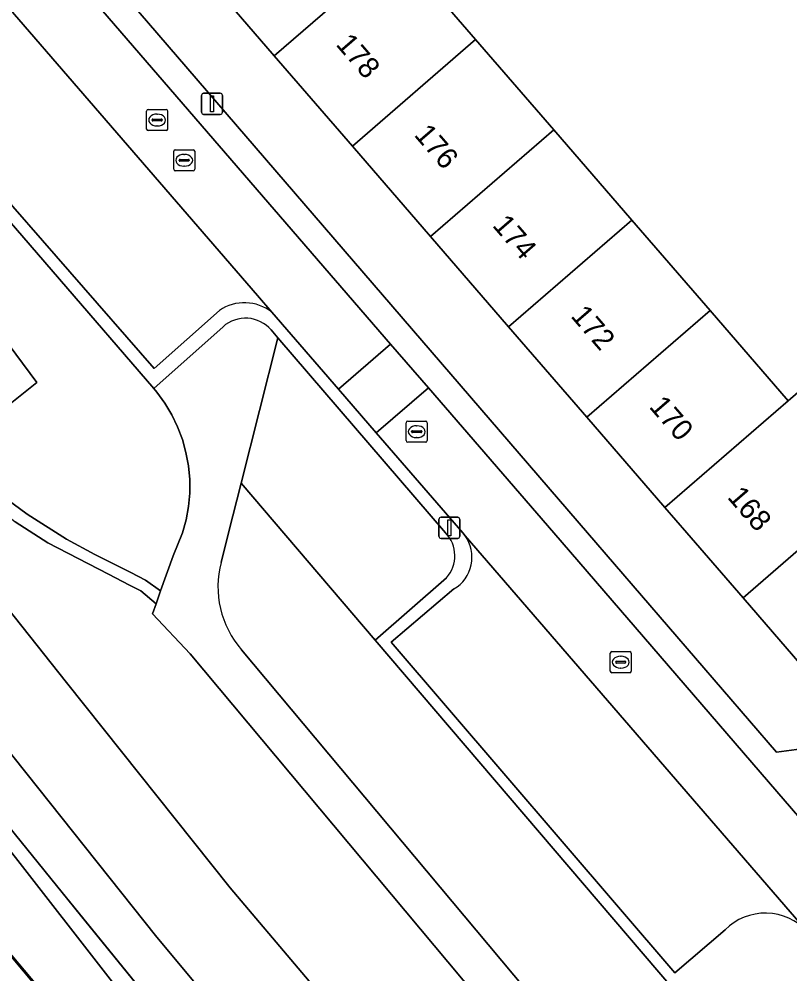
# Model space of a CAD drawing. Extents: x 160304 to 160955, y 383684 to 384161.
# Drawn here: x 160379.96 to 160416.53, y 383979.08 to 384024.37 of the extents above; entities that cross this region are included whole.
import ezdxf

# ---------------------------------------------------------------- set-up
doc = ezdxf.new("R2010")
doc.units = 0
for name, color, linetype in [('IMGEO_Erf', 7, 'Continuous'), ('IMGEO_Geluidsscherm', 7, 'Continuous'), ('IMGEO_Grasland_overig', 7, 'Continuous'), ('IMGEO_Greppel_droge_sloot', 7, 'Continuous'), ('IMGEO_Groenvoorziening', 7, 'Continuous'), ('IMGEO_Haag', 7, 'Continuous'), ('IMGEO_Hek', 7, 'Continuous'), ('IMGEO_Kolk', 7, 'Continuous'), ('IMGEO_Lichtmast', 7, 'Continuous'), ('IMGEO_Pand', 7, 'Continuous'), ('IMGEO_Pand_nummerreeks', 7, 'Continuous'), ('IMGEO_Parkeervlak_open', 7, 'Continuous'), ('IMGEO_Rijbaan_lokaal_open', 7, 'Continuous'), ('IMGEO_Rioolput', 7, 'Continuous'), ('IMGEO_Spoorbaan_halfverhard', 7, 'Continuous'), ('IMGEO_Struiken', 7, 'Continuous'), ('IMGEO_Voetpad_halfverhard', 7, 'Continuous'), ('IMGEO_Voetpad_open', 7, 'Continuous')]:
    doc.layers.add(name, color=color, linetype=linetype)

msp = doc.modelspace()

# ---------------------------------------------------------------- linework, layer by layer
at = {"layer": 'IMGEO_Erf'}
for points in [[(160379.304, 384049.215), (160383.087, 384044.841), (160385.422, 384046.86), (160389.03, 384042.688), (160386.695, 384040.669), (160386.794, 384040.554), (160390.502, 384036.266), (160394.207, 384031.981), (160397.915, 384027.693), (160401.622, 384023.407), (160405.329, 384019.12), (160409.036, 384014.833), (160412.742, 384010.547), (160416.449, 384006.26), (160419.459, 384008.862)], [(160366.633, 384046.782), (160406.925, 384000), (160415.887, 383989.594), (160418.503, 383989.954)], [(160418.094, 383992.539), (160414.309, 383996.917), (160411.643, 384000), (160410.602, 384001.204), (160406.895, 384005.491), (160403.188, 384009.778), (160399.482, 384014.064), (160395.775, 384018.351), (160392.068, 384022.638), (160388.361, 384026.925), (160384.655, 384031.211), (160380.948, 384035.498), (160377.241, 384039.785)]]:
    msp.add_lwpolyline(points, dxfattribs=at)
at = {"layer": 'IMGEO_Geluidsscherm'}
msp.add_lwpolyline([(160337.283, 384030.458), (160359.047, 384004.381), (160361.118, 384001.945), (160367.22, 383994.594), (160379.095, 383980.475), (160394.831, 383961.695), (160403.665, 383951.091), (160407.582, 383946.563), (160411.468, 383942.027)], dxfattribs=at)
at = {"layer": 'IMGEO_Grasland_overig'}
msp.add_lwpolyline([(160373.947, 383992.091), (160387.835, 383974.261), (160394.541, 383965.796), (160400.807, 383958.262), (160409.451, 383948.285), (160413.502, 383943.721), (160414.124, 383944.24), (160414.246, 383944.353), (160402.015, 383958.333), (160398.359, 383962.83), (160383.147, 383981.543), (160377.767, 383988.161)], dxfattribs=at)
at = {"layer": 'IMGEO_Greppel_droge_sloot'}
for points in [[(160500, 383868.292), (160499.844, 383868.426), (160491.37, 383875.548), (160482.322, 383883.58), (160480.673, 383885.044), (160471.059, 383893.924), (160455.21, 383909.411), (160438.969, 383926.193), (160430.579, 383935.188), (160416.266, 383951.788), (160406.97, 383963.092), (160389.971, 383983.164), (160382.21, 383992.911), (160376.565, 384000), (160374.735, 384002.298), (160368.404, 384010.249), (160347.988, 384037.853)], [(160346.589, 384036.832), (160352.018, 384025.775), (160366.262, 384006.221), (160371.217, 384000), (160386.494, 383980.821), (160404.058, 383959.794), (160413.605, 383948.881), (160427.491, 383932.216), (160436.096, 383922.678), (160452.087, 383906.656), (160468.372, 383890.76), (160477.984, 383881.802), (160489.609, 383871.764), (160495.305, 383866.693)]]:
    msp.add_lwpolyline(points, dxfattribs=at)
at = {"layer": 'IMGEO_Groenvoorziening'}
for points in [[(160347.988, 384037.853), (160368.404, 384010.249), (160374.735, 384002.298), (160376.565, 384000), (160382.21, 383992.911), (160389.971, 383983.164), (160406.97, 383963.092), (160416.266, 383951.788), (160430.579, 383935.188), (160438.969, 383926.193), (160455.21, 383909.411), (160471.059, 383893.924), (160480.673, 383885.044), (160482.322, 383883.58), (160491.37, 383875.548), (160499.844, 383868.426), (160500, 383868.292)], [(160495.305, 383866.693), (160489.609, 383871.764), (160477.984, 383881.802), (160468.372, 383890.76), (160452.087, 383906.656), (160436.096, 383922.678), (160427.491, 383932.216), (160413.605, 383948.881), (160404.058, 383959.794), (160386.494, 383980.821), (160371.217, 384000), (160366.262, 384006.221), (160352.018, 384025.775), (160346.589, 384036.832)], [(160378.468, 384002.269), (160380.346, 384000.883), (160382.213, 383999.699), (160383.553, 383998.976), (160384.379, 383998.563), (160385.258, 383998.124), (160385.953, 383997.763), (160386.679, 383997.251), (160387.266, 383998.907), (160387.719, 384000), (160387.888, 384000.62), (160388.001, 384001.253), (160388.057, 384001.893), (160388.056, 384002.536), (160387.997, 384003.176), (160387.881, 384003.808), (160387.709, 384004.428), (160387.483, 384005.029), (160387.203, 384005.608), (160386.874, 384006.16), (160386.496, 384006.68), (160386.36, 384006.845), (160372.913, 384022.406)], [(160370.777, 384020.632), (160380.812, 384007.137), (160378.817, 384005.548)], [(160378.817, 384005.548), (160380.812, 384007.137), (160370.777, 384020.632)], [(160400.188, 384000), (160392.242, 384009.254), (160390.498, 384002.361), (160396.861, 383994.912), (160400.235, 383997.872)], [(160409.229, 383975.404), (160411.707, 383977.533), (160396.861, 383994.912), (160390.498, 384002.361), (160389.901, 384000), (160389.548, 383998.604)], [(160447.338, 383923.446), (160388.085, 383994.267), (160386.292, 383996.161), (160386.459, 383996.631), (160385.733, 383997.245), (160385.207, 383997.523), (160384.211, 383998.05), (160381.32, 383999.528), (160379.778, 384000.533)], [(160390.511, 383994.462), (160406.355, 383975.532)], [(160377.767, 383988.161), (160383.147, 383981.543), (160398.359, 383962.83), (160402.015, 383958.333), (160414.246, 383944.353), (160425.857, 383931.082), (160435.125, 383920.904), (160442.778, 383912.907), (160446.69, 383908.992), (160450.658, 383905.135), (160487.621, 383870.467), (160487.683, 383870.417), (160495.827, 383863.852), (160496.977, 383862.925), (160503.928, 383859.415), (160516.251, 383853.192), (160518.879, 383851.372), (160551.794, 383826.847)]]:
    msp.add_lwpolyline(points, dxfattribs=at)
for centre, radius, start, end in [((160399.087, 383998.911), 1.549, 317.8583, 44.6722), ((160393.95, 383997.444), 4.552, 165.2419, 220.9351)]:
    msp.add_arc(centre, radius, start, end, dxfattribs=at)
at = {"layer": 'IMGEO_Haag'}
for points in [[(160409.229, 383975.404), (160411.707, 383977.533), (160396.861, 383994.912), (160390.498, 384002.361), (160389.901, 384000), (160389.548, 383998.604)], [(160390.511, 383994.462), (160406.355, 383975.532)]]:
    msp.add_lwpolyline(points, dxfattribs=at)
msp.add_arc((160393.95, 383997.444), 4.552, 165.2419, 220.9351, dxfattribs=at)
at = {"layer": 'IMGEO_Hek'}
msp.add_lwpolyline([(160496.977, 383862.925), (160487.621, 383870.467), (160450.658, 383905.135), (160446.69, 383908.992), (160442.778, 383912.907), (160435.125, 383920.904), (160425.857, 383931.082), (160402.015, 383958.333), (160377.767, 383988.161), (160365.932, 384005.469), (160340.965, 384039.679), (160336.678, 384040.252)], dxfattribs=at)
at = {"layer": 'IMGEO_Kolk'}
for p, q in [((160387.297, 384017.251), (160387.297, 384018.103)), ((160387.372, 384018.177), (160388.224, 384018.177)), ((160388.298, 384018.103), (160388.298, 384017.251)), ((160387.556, 384017.671), (160387.556, 384017.683)), ((160387.994, 384017.634), (160387.596, 384017.634)), ((160387.599, 384017.72), (160387.997, 384017.72)), ((160387.785, 384017.957), (160387.81, 384017.957)), ((160388.04, 384017.683), (160388.04, 384017.671)), ((160388.224, 384017.177), (160387.372, 384017.177)), ((160387.808, 384017.397), (160387.783, 384017.397)), ((160398.327, 384004.376), (160398.327, 384005.228)), ((160398.402, 384005.302), (160399.254, 384005.302)), ((160398.815, 384005.082), (160398.84, 384005.082)), ((160399.328, 384005.228), (160399.328, 384004.376)), ((160398.586, 384004.796), (160398.586, 384004.808)), ((160399.024, 384004.759), (160398.626, 384004.759)), ((160398.629, 384004.845), (160399.027, 384004.845)), ((160398.838, 384004.522), (160398.813, 384004.522)), ((160399.07, 384004.808), (160399.07, 384004.796)), ((160399.254, 384004.302), (160398.402, 384004.302)), ((160408.006, 383993.443), (160408.006, 383994.295)), ((160408.081, 383994.369), (160408.933, 383994.369)), ((160408.494, 383994.149), (160408.519, 383994.149)), ((160409.007, 383994.295), (160409.007, 383993.443)), ((160408.265, 383993.863), (160408.265, 383993.875)), ((160408.703, 383993.826), (160408.305, 383993.826)), ((160408.308, 383993.912), (160408.706, 383993.912)), ((160408.517, 383993.589), (160408.492, 383993.589)), ((160408.749, 383993.875), (160408.749, 383993.863)), ((160408.933, 383993.369), (160408.081, 383993.369))]:
    msp.add_line(p, q, dxfattribs=at)
for points in [[(160387.297, 384017.251), (160387.297, 384018.103)], [(160387.372, 384018.177), (160388.224, 384018.177)], [(160388.298, 384018.103), (160388.298, 384017.251)], [(160388.224, 384017.177), (160387.372, 384017.177)], [(160398.327, 384004.376), (160398.327, 384005.228)], [(160398.402, 384005.302), (160399.254, 384005.302)], [(160399.328, 384005.228), (160399.328, 384004.376)], [(160399.254, 384004.302), (160398.402, 384004.302)], [(160408.006, 383993.443), (160408.006, 383994.295)], [(160408.081, 383994.369), (160408.933, 383994.369)], [(160409.007, 383994.295), (160409.007, 383993.443)], [(160408.933, 383993.369), (160408.081, 383993.369)]]:
    msp.add_lwpolyline(points, dxfattribs=at)
for centre, radius, start, end in [((160387.374, 384018.101), 0.0765, 91.552, 178.448), ((160387.374, 384018.101), 0.0765, 91.552, 178.448), ((160388.222, 384018.101), 0.0765, 1.552, 88.448), ((160388.222, 384018.101), 0.0765, 1.552, 88.448), ((160387.596, 384017.68), 0.0403, 85.8775, 175.7526), ((160387.593, 384017.67), 0.0366, 178.938, 274.7102), ((160387.997, 384017.677), 0.043, 264.8664, 352.4533), ((160388.001, 384017.682), 0.0386, 1.7309, 96.639), ((160387.374, 384017.253), 0.0765, 181.552, 268.448), ((160387.374, 384017.253), 0.0765, 181.552, 268.448), ((160388.222, 384017.253), 0.0765, 271.552, 358.448), ((160388.222, 384017.253), 0.0765, 271.552, 358.448), ((160398.404, 384005.226), 0.0765, 91.552, 178.448), ((160398.404, 384005.226), 0.0765, 91.552, 178.448), ((160399.252, 384005.226), 0.0765, 1.552, 88.448), ((160399.252, 384005.226), 0.0765, 1.552, 88.448), ((160398.626, 384004.805), 0.0403, 85.8775, 175.7526), ((160398.623, 384004.795), 0.0366, 178.938, 274.7102), ((160399.027, 384004.802), 0.043, 264.8664, 352.4533), ((160399.031, 384004.807), 0.0386, 1.7309, 96.639), ((160398.404, 384004.378), 0.0765, 181.552, 268.448), ((160398.404, 384004.378), 0.0765, 181.552, 268.448), ((160399.252, 384004.378), 0.0765, 271.552, 358.448), ((160399.252, 384004.378), 0.0765, 271.552, 358.448), ((160408.083, 383994.293), 0.0765, 91.552, 178.448), ((160408.083, 383994.293), 0.0765, 91.552, 178.448), ((160408.931, 383994.293), 0.0765, 1.552, 88.448), ((160408.931, 383994.293), 0.0765, 1.552, 88.448), ((160408.305, 383993.872), 0.0403, 85.8775, 175.7526), ((160408.302, 383993.862), 0.0366, 178.938, 274.7102), ((160408.706, 383993.869), 0.043, 264.8664, 352.4533), ((160408.71, 383993.874), 0.0386, 1.7309, 96.639), ((160408.083, 383993.445), 0.0765, 181.552, 268.448), ((160408.083, 383993.445), 0.0765, 181.552, 268.448), ((160408.931, 383993.445), 0.0765, 271.552, 358.448), ((160408.931, 383993.445), 0.0765, 271.552, 358.448)]:
    msp.add_arc(centre, radius, start, end, dxfattribs=at)
for centre, major_axis, ratio, start_param, end_param in [((160387.784, 384017.677), (-0.387, 0.002), 0.722429, 4.712389, 7.853982), ((160387.809, 384017.677), (-0.39, 0.002), 0.717154, 1.570796, 4.712389), ((160398.814, 384004.802), (-0.387, 0.002), 0.722429, 4.712389, 7.853982), ((160398.839, 384004.802), (-0.39, 0.002), 0.717154, 1.570796, 4.712389), ((160408.493, 383993.869), (-0.387, 0.002), 0.722429, 4.712389, 7.853982), ((160408.518, 383993.869), (-0.39, 0.002), 0.717154, 1.570796, 4.712389)]:
    msp.add_ellipse(centre, major_axis=major_axis, ratio=ratio, start_param=start_param, end_param=end_param, dxfattribs=at)
at = {"layer": 'IMGEO_Lichtmast'}
for p, q in [((160388.62, 384019.953), (160388.62, 384020.753)), ((160388.62, 384020.753), (160388.62, 384019.953)), ((160388.72, 384020.853), (160389.51, 384020.853)), ((160389.51, 384020.853), (160388.72, 384020.853)), ((160389.61, 384020.753), (160389.61, 384019.953)), ((160389.61, 384019.953), (160389.61, 384020.753)), ((160389.51, 384019.853), (160388.72, 384019.853)), ((160388.72, 384019.853), (160389.51, 384019.853)), ((160399.881, 383999.841), (160399.881, 384000.641)), ((160399.881, 384000.641), (160399.881, 383999.841)), ((160399.981, 384000.741), (160400.771, 384000.741)), ((160400.771, 384000.741), (160399.981, 384000.741)), ((160400.871, 384000.641), (160400.871, 383999.841)), ((160400.871, 383999.841), (160400.871, 384000.641)), ((160400.771, 383999.741), (160399.981, 383999.741)), ((160399.981, 383999.741), (160400.771, 383999.741))]:
    msp.add_line(p, q, dxfattribs=at)
for points in [[(160389.04, 384020.728), (160389.19, 384020.728), (160389.19, 384019.978), (160389.04, 384019.978), (160389.04, 384020.728)], [(160400.301, 384000.616), (160400.451, 384000.616), (160400.451, 383999.866), (160400.301, 383999.866), (160400.301, 384000.616)]]:
    msp.add_lwpolyline(points, dxfattribs=at)
for centre, start, end in [((160388.72, 384020.753), 90, 180), ((160388.72, 384020.753), 90, 180), ((160389.51, 384020.753), 0, 90), ((160389.51, 384020.753), 360, 90), ((160388.72, 384019.953), 180, 270), ((160388.72, 384019.953), 180, 270), ((160389.51, 384019.953), 270, 0), ((160389.51, 384019.953), 270, 0), ((160399.981, 384000.641), 90, 180), ((160399.981, 384000.641), 90, 180), ((160400.771, 384000.641), 0, 90), ((160400.771, 384000.641), 360, 90), ((160399.981, 383999.841), 180, 270), ((160399.981, 383999.841), 180, 270), ((160400.771, 383999.841), 270, 0), ((160400.771, 383999.841), 270, 0)]:
    msp.add_arc(centre, 0.1, start, end, dxfattribs=at)
at = {"layer": 'IMGEO_Pand'}
for points in [[(160388.361, 384026.925), (160392.068, 384022.638), (160397.915, 384027.693), (160394.207, 384031.981)], [(160397.915, 384027.693), (160392.068, 384022.638), (160395.775, 384018.351), (160401.622, 384023.407)], [(160405.329, 384019.12), (160401.622, 384023.407), (160395.775, 384018.351), (160399.482, 384014.064)], [(160409.036, 384014.833), (160405.329, 384019.12), (160399.482, 384014.064), (160403.188, 384009.778)], [(160409.036, 384014.833), (160403.188, 384009.778), (160406.895, 384005.491), (160412.742, 384010.547)], [(160410.602, 384001.204), (160416.449, 384006.26), (160412.742, 384010.547), (160406.895, 384005.491)], [(160420.156, 384001.973), (160423.166, 384004.575), (160419.459, 384008.862), (160416.449, 384006.26), (160410.602, 384001.204), (160411.643, 384000), (160414.309, 383996.917), (160417.874, 384000)], [(160420.156, 384001.973), (160417.874, 384000), (160414.309, 383996.917), (160418.094, 383992.539), (160423.941, 383997.595), (160421.862, 384000), (160420.671, 384001.378)]]:
    msp.add_lwpolyline(points, close=True, dxfattribs=at)
at = {"layer": 'IMGEO_Parkeervlak_open'}
for points in [[(160391.959, 384010.465), (160391.267, 384011.265), (160370.932, 384034.776)], [(160369.862, 384032.915), (160369.487, 384032.615), (160366.739, 384030.257), (160378.355, 384016.973), (160386.37, 384007.804), (160389.465, 384010.549)], [(160417.354, 383981.089), (160401.126, 383999.866)], [(160400.594, 383997.34), (160397.62, 383994.816), (160411.072, 383979.14), (160413.461, 383981.17)]]:
    msp.add_lwpolyline(points, dxfattribs=at)
for centre, radius, start, end in [((160390.655, 384008.821), 2.098, 51.583, 124.5589), ((160399.688, 383998.85), 1.761, 300.9678, 35.2458), ((160415.369, 383979.283), 2.684, 42.2971, 135.319)]:
    msp.add_arc(centre, radius, start, end, dxfattribs=at)
at = {"layer": 'IMGEO_Rijbaan_lokaal_open'}
for points in [[(160364.754, 384046.943), (160362.283, 384044.777), (160370.313, 384035.491), (160370.932, 384034.776), (160391.267, 384011.265), (160391.959, 384010.465), (160395.114, 384006.817), (160397.588, 384008.955)], [(160399.379, 384006.883), (160397.588, 384008.955), (160395.114, 384006.817), (160396.906, 384004.745)], [(160405.328, 384000), (160399.379, 384006.883), (160396.906, 384004.745), (160401.01, 384000), (160401.126, 383999.866), (160417.354, 383981.089), (160419.771, 383983.265)]]:
    msp.add_lwpolyline(points, close=True, dxfattribs=at)
at = {"layer": 'IMGEO_Rioolput'}
for p, q in [((160386.011, 384019.159), (160386.011, 384020.011)), ((160386.086, 384020.085), (160386.938, 384020.085)), ((160386.499, 384019.865), (160386.524, 384019.865)), ((160387.012, 384020.011), (160387.012, 384019.159)), ((160386.27, 384019.579), (160386.27, 384019.591)), ((160386.708, 384019.542), (160386.31, 384019.542)), ((160386.313, 384019.628), (160386.711, 384019.628)), ((160386.754, 384019.591), (160386.754, 384019.579)), ((160386.938, 384019.085), (160386.086, 384019.085)), ((160386.522, 384019.305), (160386.497, 384019.305))]:
    msp.add_line(p, q, dxfattribs=at)
for points in [[(160386.011, 384019.159), (160386.011, 384020.011)], [(160386.086, 384020.085), (160386.938, 384020.085)], [(160387.012, 384020.011), (160387.012, 384019.159)], [(160386.938, 384019.085), (160386.086, 384019.085)]]:
    msp.add_lwpolyline(points, dxfattribs=at)
for centre, radius, start, end in [((160386.088, 384020.009), 0.0765, 91.552, 178.448), ((160386.088, 384020.009), 0.0765, 91.552, 178.448), ((160386.936, 384020.009), 0.0765, 1.552, 88.448), ((160386.936, 384020.009), 0.0765, 1.552, 88.448), ((160386.31, 384019.588), 0.0403, 85.8775, 175.7526), ((160386.307, 384019.578), 0.0366, 178.938, 274.7102), ((160386.711, 384019.585), 0.043, 264.8664, 352.4533), ((160386.715, 384019.59), 0.0386, 1.7309, 96.639), ((160386.088, 384019.161), 0.0765, 181.552, 268.448), ((160386.088, 384019.161), 0.0765, 181.552, 268.448), ((160386.936, 384019.161), 0.0765, 271.552, 358.448), ((160386.936, 384019.161), 0.0765, 271.552, 358.448)]:
    msp.add_arc(centre, radius, start, end, dxfattribs=at)
for centre, major_axis, ratio, start_param, end_param in [((160386.498, 384019.585), (-0.387, 0.002), 0.722429, 4.712389, 7.853982), ((160386.523, 384019.585), (-0.39, 0.002), 0.717154, 1.570796, 4.712389)]:
    msp.add_ellipse(centre, major_axis=major_axis, ratio=ratio, start_param=start_param, end_param=end_param, dxfattribs=at)
at = {"layer": 'IMGEO_Spoorbaan_halfverhard'}
msp.add_lwpolyline([(160351.342, 383971.506), (160389.483, 383923.713), (160391.638, 383925.508), (160396.756, 383929.772), (160400.081, 383932.541), (160404.629, 383936.33), (160407.879, 383939.037), (160409.775, 383940.617), (160411.6, 383942.137), (160411.599, 383942.138), (160394.029, 383962.815), (160361.118, 384001.945)], dxfattribs=at)
at = {"layer": 'IMGEO_Struiken'}
msp.add_lwpolyline([(160332.154, 384036.813), (160332.113, 384036.783), (160334.486, 384033.929), (160361.118, 384001.945), (160394.029, 383962.815), (160411.599, 383942.138), (160411.6, 383942.137), (160413.502, 383943.721), (160409.451, 383948.285), (160400.807, 383958.262), (160394.541, 383965.796), (160387.835, 383974.261), (160373.947, 383992.091), (160369.822, 383997.497), (160366.05, 384002.667), (160352.129, 384022.462), (160346.35, 384030.668), (160342.046, 384035.848), (160338.753, 384038.065), (160333.795, 384038.435), (160332.314, 384037.293), (160332.485, 384037.061)], close=True, dxfattribs=at)
at = {"layer": 'IMGEO_Voetpad_halfverhard'}
for points in [[(160389.638, 384009.779), (160386.36, 384006.845), (160386.496, 384006.68), (160386.874, 384006.16), (160387.203, 384005.608), (160387.483, 384005.029), (160387.709, 384004.428), (160387.881, 384003.808), (160387.997, 384003.176), (160388.056, 384002.536), (160388.057, 384001.893), (160388.001, 384001.253), (160387.888, 384000.62), (160387.719, 384000), (160387.266, 383998.907), (160386.679, 383997.251), (160386.459, 383996.631), (160386.292, 383996.161), (160388.085, 383994.267), (160447.338, 383923.446)], [(160389.548, 383998.604), (160389.901, 384000), (160390.498, 384002.361), (160392.242, 384009.254), (160391.919, 384009.63)], [(160406.355, 383975.532), (160390.511, 383994.462)]]:
    msp.add_lwpolyline(points, dxfattribs=at)
msp.add_lwpolyline([(160376.999, 384004.101), (160376.517, 384003.717), (160377.796, 384002.111), (160379.778, 384000.533), (160381.32, 383999.528), (160384.211, 383998.05), (160385.207, 383997.523), (160385.733, 383997.245), (160386.459, 383996.631), (160386.679, 383997.251), (160385.953, 383997.763), (160385.258, 383998.124), (160384.379, 383998.563), (160383.553, 383998.976), (160382.213, 383999.699), (160380.346, 384000.883), (160378.468, 384002.269), (160377.765, 384003.139)], close=True, dxfattribs=at)
for centre, radius, start, end in [((160390.706, 384008.588), 1.599, 40.655, 131.8703), ((160393.95, 383997.444), 4.552, 165.2419, 220.9351)]:
    msp.add_arc(centre, radius, start, end, dxfattribs=at)
at = {"layer": 'IMGEO_Voetpad_open'}
for points in [[(160364.754, 384046.943), (160397.588, 384008.955), (160399.379, 384006.883), (160405.328, 384000), (160419.771, 383983.265), (160422.038, 383985.305), (160420.449, 383987.142), (160418.503, 383989.954), (160415.887, 383989.594), (160406.925, 384000), (160366.633, 384046.782)], [(160389.465, 384010.549), (160386.37, 384007.804), (160378.355, 384016.973), (160366.739, 384030.257), (160369.487, 384032.615)], [(160372.913, 384022.406), (160386.36, 384006.845), (160389.638, 384009.779)], [(160401.126, 383999.866), (160401.01, 384000), (160396.906, 384004.745), (160395.114, 384006.817), (160391.959, 384010.465)], [(160391.919, 384009.63), (160392.242, 384009.254), (160400.188, 384000)], [(160400.235, 383997.872), (160396.861, 383994.912), (160411.707, 383977.533), (160412.996, 383975.993), (160414.102, 383974.703), (160414.61, 383975.139), (160417.19, 383977.308)], [(160413.461, 383981.17), (160411.072, 383979.14), (160397.62, 383994.816), (160400.594, 383997.34)]]:
    msp.add_lwpolyline(points, dxfattribs=at)
for centre, radius, start, end in [((160390.655, 384008.821), 2.098, 51.583, 124.5589), ((160390.706, 384008.588), 1.599, 40.655, 131.8703), ((160399.087, 383998.911), 1.549, 317.8583, 44.6722), ((160399.688, 383998.85), 1.761, 300.9678, 35.2458), ((160415.369, 383979.283), 2.684, 42.2971, 135.319)]:
    msp.add_arc(centre, radius, start, end, dxfattribs=at)

# ---------------------------------------------------------------- texts
at = {"layer": 'IMGEO_Pand_nummerreeks'}
for s, rotation, p in [('178', 310.8517, (160394.954, 384023.156)), ('176', 310.8517, (160398.666, 384018.863)), ('174', 310.8517, (160402.381, 384014.567)), ('172', 310.8517, (160406.095, 384010.272)), ('170', 310.8517, (160409.813, 384005.972)), ('168', 310.8345, (160413.523, 384001.68))]:
    msp.add_text(s, height=1, rotation=rotation, dxfattribs=at).set_placement(p)

doc.saveas('drawing.dxf')
